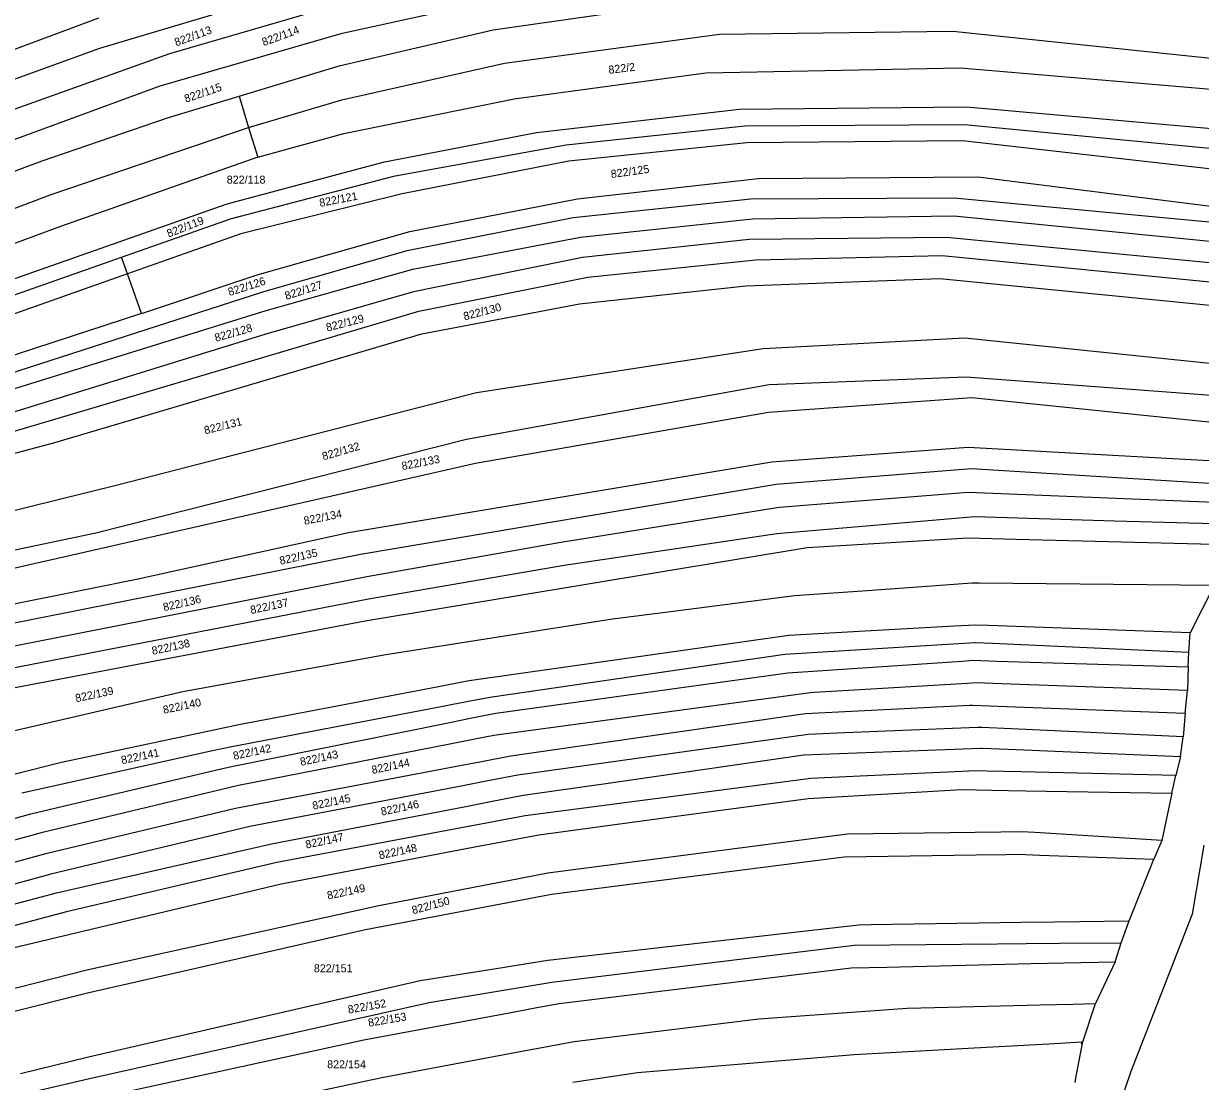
# Model space of a CAD drawing. Extents: x -580630 to -576196, y -1189024 to -1183567.
# Drawn here: x -577295.7 to -577045.8, y -1185459.8 to -1185235.3 of the extents above; entities that cross this region are included whole.
import ezdxf

# ---------------------------------------------------------------- set-up
doc = ezdxf.new("R2010")
doc.units = 0
for name, color, linetype in [('Vrstva 1', 7, 'Continuous'), ('Vrstva 13', 7, 'Continuous'), ('Vrstva 18', 7, 'Continuous'), ('Vrstva 4', 7, 'Continuous'), ('Vrstva 6', 7, 'Continuous')]:
    doc.layers.add(name, color=color, linetype=linetype)

msp = doc.modelspace()

# ---------------------------------------------------------------- linework, layer by layer
at = {"layer": 'Vrstva 1'}
for p, q in [((-577195.98, -1185236.67), (-577151.26, -1185230.19)), ((-577228.67, -1185244.27), (-577195.98, -1185236.67)), ((-577193.6, -1185243.72), (-577147.96, -1185237.55)), ((-577147.96, -1185237.55), (-577098.41, -1185236.93)), ((-577098.41, -1185236.93), (-577036.92, -1185243.39)), ((-577249.94, -1185250.73), (-577228.67, -1185244.27)), ((-577228.14, -1185251.54), (-577193.6, -1185243.72)), ((-577265.16, -1185255.36), (-577249.94, -1185250.73)), ((-577249.94, -1185250.73), (-577247.99, -1185257.41)), ((-577247.99, -1185257.41), (-577228.14, -1185251.54)), ((-577291.79, -1185264.43), (-577265.16, -1185255.36)), ((-577290.04, -1185271.7), (-577247.99, -1185257.41)), ((-577348.23, -1185285.72), (-577291.79, -1185264.43)), ((-577346.48, -1185292.79), (-577290.04, -1185271.7)), ((-577042.94, -1185354.58), (-577048.01, -1185364.64)), ((-577048.3, -1185368.7), (-577048.01, -1185364.64)), ((-577048.4, -1185371.84), (-577048.3, -1185368.7)), ((-577048.4, -1185371.84), (-577048.6, -1185376.87)), ((-577049.07, -1185381.68), (-577048.6, -1185376.87)), ((-577049.07, -1185381.68), (-577049.51, -1185386.7)), ((-577050.03, -1185390.87), (-577049.51, -1185386.7)), ((-577050.03, -1185390.87), (-577051.02, -1185394.89)), ((-577051.9, -1185398.64), (-577051.02, -1185394.89)), ((-577051.9, -1185398.64), (-577054.01, -1185408.69)), ((-577054.01, -1185408.69), (-577055.7, -1185412.68)), ((-577060.98, -1185425.7), (-577055.7, -1185412.68)), ((-577062.62, -1185430.38), (-577060.98, -1185425.7)), ((-577063.93, -1185434.4), (-577062.62, -1185430.38)), ((-577063.93, -1185434.4), (-577068.12, -1185443.28)), ((-577070.79, -1185451.4), (-577068.12, -1185443.28)), ((-577072.26, -1185459.1), (-577070.93, -1185452.15)), ((-577070.93, -1185452.15), (-577070.79, -1185451.4)), ((-577072.44, -1185460.06), (-577072.26, -1185459.1))]:
    msp.add_line(p, q, dxfattribs=at)
at = {"layer": 'Vrstva 13'}
for p, q in [((-577045.08, -1185409.66), (-577047.56, -1185424.29)), ((-577047.56, -1185424.29), (-577060.63, -1185457.67)), ((-577060.63, -1185457.67), (-577068.8, -1185482.09))]:
    msp.add_line(p, q, dxfattribs=at)
at = {"layer": 'Vrstva 4'}
msp.add_line((-577070.93, -1185452.15), (-577071.1, -1185451.42), dxfattribs=at)
at = {"layer": 'Vrstva 6'}
for p, q in [((-577225.98, -1185224.6), (-577279.63, -1185240.65)), ((-577195.67, -1185230.3), (-577228.36, -1185237.49)), ((-577264.65, -1185241.65), (-577230.51, -1185231.8)), ((-577356.86, -1185262.65), (-577279.75, -1185234.14)), ((-577228.36, -1185237.49), (-577266.81, -1185248.6)), ((-577279.63, -1185240.65), (-577428.39, -1185294.25)), ((-577306.69, -1185256.67), (-577264.65, -1185241.65)), ((-577150.83, -1185245.77), (-577096.75, -1185244.75)), ((-577096.75, -1185244.75), (-577036.69, -1185249.83)), ((-577191.54, -1185251.33), (-577150.83, -1185245.77)), ((-577266.81, -1185248.6), (-577363.54, -1185284.08)), ((-577227.72, -1185258.63), (-577191.54, -1185251.33)), ((-577095.49, -1185253.07), (-577143.71, -1185253.58)), ((-577036.22, -1185258.31), (-577095.49, -1185253.07)), ((-577143.71, -1185253.58), (-577186.83, -1185258.53)), ((-577247.99, -1185257.41), (-577245.99, -1185263.69)), ((-577180.52, -1185261.07), (-577142.59, -1185257.06)), ((-577142.59, -1185257.06), (-577095.92, -1185256.75)), ((-577095.92, -1185256.75), (-577034.72, -1185262.66)), ((-577245.99, -1185263.69), (-577227.72, -1185258.63)), ((-577186.83, -1185258.53), (-577219.42, -1185264.8)), ((-577142.17, -1185260.64), (-577179.96, -1185264.55)), ((-577096.37, -1185260.23), (-577142.17, -1185260.64)), ((-577032.89, -1185267.43), (-577096.37, -1185260.23)), ((-577216.81, -1185267.66), (-577180.52, -1185261.07)), ((-577245.99, -1185263.69), (-577287.88, -1185278.39)), ((-577219.42, -1185264.8), (-577252.59, -1185273.62)), ((-577179.96, -1185264.55), (-577215.32, -1185271.44)), ((-577251.55, -1185276.7), (-577216.81, -1185267.66)), ((-577139.76, -1185268.18), (-577093.09, -1185267.86)), ((-577093.09, -1185267.86), (-577032.52, -1185275.44)), ((-577178.1, -1185272.49), (-577139.76, -1185268.18)), ((-577215.32, -1185271.44), (-577249.56, -1185279.97)), ((-577213.67, -1185279.48), (-577178.1, -1185272.49)), ((-577179.04, -1185276.51), (-577141.3, -1185272.5)), ((-577141.3, -1185272.5), (-577098.12, -1185272.29)), ((-577098.12, -1185272.29), (-577032.65, -1185278.44)), ((-577252.59, -1185273.62), (-577345.1, -1185306.23)), ((-577274.95, -1185284.92), (-577251.55, -1185276.7)), ((-577214.3, -1185283.51), (-577179.04, -1185276.51)), ((-577177.47, -1185280.66), (-577140.97, -1185276.75)), ((-577140.97, -1185276.75), (-577098.21, -1185276.13)), ((-577098.21, -1185276.13), (-577032.99, -1185282.61)), ((-577287.88, -1185278.39), (-577347, -1185300.09)), ((-577249.56, -1185279.97), (-577273.68, -1185288.46)), ((-577246.15, -1185288.64), (-577213.67, -1185279.48)), ((-577213.04, -1185287.45), (-577177.47, -1185280.66)), ((-577141.67, -1185281.17), (-577177.04, -1185284.97)), ((-577099.72, -1185280.76), (-577141.67, -1185281.17)), ((-577033.44, -1185287.08), (-577099.72, -1185280.76)), ((-577348.19, -1185310.63), (-577274.95, -1185284.92)), ((-577273.68, -1185288.46), (-577274.95, -1185284.92)), ((-577244.93, -1185292.25), (-577214.3, -1185283.51)), ((-577177.04, -1185284.97), (-577212.91, -1185292.29)), ((-577175.91, -1185289.18), (-577140.24, -1185285.48)), ((-577140.24, -1185285.48), (-577100.65, -1185284.56)), ((-577100.65, -1185284.56), (-577033.82, -1185291.12)), ((-577244.19, -1185296.2), (-577213.04, -1185287.45)), ((-577273.68, -1185288.46), (-577336.94, -1185310.73)), ((-577270.67, -1185296.86), (-577273.68, -1185288.46)), ((-577270.67, -1185296.86), (-577246.15, -1185288.64)), ((-577211.78, -1185296.39), (-577175.91, -1185289.18)), ((-577142.38, -1185290.98), (-577101.15, -1185289.44)), ((-577101.15, -1185289.44), (-577035.33, -1185295.94)), ((-577329.44, -1185319.52), (-577244.93, -1185292.25)), ((-577212.91, -1185292.29), (-577244.27, -1185301.24)), ((-577177.64, -1185294.79), (-577142.38, -1185290.98)), ((-577211.16, -1185301.16), (-577177.64, -1185294.79)), ((-577328.69, -1185322.43), (-577244.19, -1185296.2)), ((-577270.67, -1185296.86), (-577327.07, -1185315.2)), ((-577319.42, -1185328.27), (-577211.78, -1185296.39)), ((-577244.27, -1185301.24), (-577322.5, -1185325.41)), ((-577289.08, -1185324.21), (-577211.16, -1185301.16)), ((-577095.82, -1185302.12), (-577138.7, -1185304.34)), ((-577040.41, -1185307.83), (-577095.82, -1185302.12)), ((-577138.7, -1185304.34), (-577199.56, -1185313.69)), ((-577095.54, -1185310.34), (-577137.38, -1185311.98)), ((-577042.56, -1185314.35), (-577095.54, -1185310.34)), ((-577137.38, -1185311.98), (-577201.64, -1185323.61)), ((-577199.56, -1185313.69), (-577275.79, -1185333.3)), ((-577094.37, -1185314.77), (-577137.55, -1185317.86)), ((-577042.69, -1185320.05), (-577094.37, -1185314.77)), ((-577137.55, -1185317.86), (-577199.75, -1185328.66)), ((-577389.83, -1185350.96), (-577289.08, -1185324.21)), ((-577201.64, -1185323.61), (-577280.39, -1185343.46)), ((-577095.12, -1185325.32), (-577136.86, -1185328.41)), ((-577042.72, -1185328.18), (-577095.12, -1185325.32)), ((-577199.75, -1185328.66), (-577314.8, -1185354.79)), ((-577136.86, -1185328.41), (-577226.72, -1185343.43)), ((-577135.94, -1185333.04), (-577094.51, -1185329.75)), ((-577094.51, -1185329.75), (-577042.79, -1185332.9)), ((-577224.16, -1185347.95), (-577135.94, -1185333.04)), ((-577275.79, -1185333.3), (-577337.63, -1185348.5)), ((-577095.15, -1185334.84), (-577135.25, -1185338.03)), ((-577042.79, -1185336.94), (-577095.15, -1185334.84)), ((-577135.25, -1185338.03), (-577181.63, -1185345.44)), ((-577093.72, -1185340.01), (-577135.77, -1185343.62)), ((-577064.05, -1185340.89), (-577093.72, -1185340.01)), ((-577042.9, -1185341.51), (-577064.05, -1185340.89)), ((-577280.39, -1185343.46), (-577315.66, -1185350.86)), ((-577226.72, -1185343.43), (-577271.75, -1185353.3)), ((-577181.63, -1185345.44), (-577222.84, -1185352.74)), ((-577135.77, -1185343.62), (-577180.91, -1185350.3)), ((-577095.17, -1185344.52), (-577129.3, -1185346.58)), ((-577085.03, -1185344.78), (-577095.17, -1185344.52)), ((-577043, -1185345.87), (-577085.03, -1185344.78)), ((-577311.03, -1185365.13), (-577224.16, -1185347.95)), ((-577129.3, -1185346.58), (-577223.17, -1185362.12)), ((-577180.91, -1185350.3), (-577222.45, -1185357.51)), ((-577222.84, -1185352.74), (-577310.75, -1185370.02)), ((-577271.75, -1185353.3), (-577312.87, -1185361.53)), ((-577100.01, -1185354.5), (-577117.6, -1185355.75)), ((-577094.38, -1185354.1), (-577100.01, -1185354.5)), ((-577092.8, -1185354.11), (-577094.38, -1185354.1)), ((-577042.94, -1185354.58), (-577092.8, -1185354.11)), ((-577222.45, -1185357.51), (-577309.73, -1185374.37)), ((-577132.01, -1185356.78), (-577158.81, -1185360.2)), ((-577117.6, -1185355.75), (-577132.01, -1185356.78)), ((-577158.81, -1185360.2), (-577170.67, -1185361.72)), ((-577223.17, -1185362.12), (-577306.75, -1185378.07)), ((-577170.67, -1185361.72), (-577219.22, -1185369.37)), ((-577093.56, -1185362.99), (-577098.03, -1185363.23)), ((-577090.79, -1185363.09), (-577093.56, -1185362.99)), ((-577048.01, -1185364.64), (-577090.79, -1185363.09)), ((-577133.24, -1185365.15), (-577201.11, -1185374.82)), ((-577117.02, -1185364.27), (-577133.24, -1185365.15)), ((-577098.03, -1185363.23), (-577117.02, -1185364.27)), ((-577134.09, -1185369.17), (-577097.22, -1185366.87)), ((-577097.22, -1185366.87), (-577093.68, -1185366.65)), ((-577093.68, -1185366.65), (-577089.96, -1185366.82)), ((-577089.96, -1185366.82), (-577048.3, -1185368.7)), ((-577219.22, -1185369.37), (-577261.93, -1185377.12)), ((-577149.13, -1185371.35), (-577134.09, -1185369.17)), ((-577133.45, -1185373.13), (-577096.38, -1185370.61)), ((-577096.38, -1185370.61), (-577094.07, -1185370.45)), ((-577094.07, -1185370.45), (-577089.12, -1185370.6)), ((-577089.12, -1185370.6), (-577048.4, -1185371.84)), ((-577196.23, -1185378.17), (-577149.13, -1185371.35)), ((-577202.26, -1185375.04), (-577207.64, -1185376.07)), ((-577201.11, -1185374.82), (-577202.26, -1185375.04)), ((-577195.45, -1185381.66), (-577133.45, -1185373.13)), ((-577095.3, -1185375.37), (-577127.79, -1185377.27)), ((-577093.34, -1185375.26), (-577095.3, -1185375.37)), ((-577088.04, -1185375.45), (-577093.34, -1185375.26)), ((-577048.6, -1185376.87), (-577088.04, -1185375.45)), ((-577261.93, -1185377.12), (-577305.37, -1185387.23)), ((-577207.64, -1185376.07), (-577241.77, -1185382.58)), ((-577128.61, -1185377.32), (-577195.85, -1185386.38)), ((-577127.79, -1185377.27), (-577128.61, -1185377.32)), ((-577251.47, -1185388.71), (-577206.7, -1185380.17)), ((-577206.7, -1185380.17), (-577201.34, -1185379.15)), ((-577201.34, -1185379.15), (-577196.23, -1185378.17)), ((-577129.71, -1185381.77), (-577094.8, -1185379.96)), ((-577094.8, -1185379.96), (-577094.25, -1185379.98)), ((-577094.25, -1185379.98), (-577086.97, -1185380.25)), ((-577086.97, -1185380.25), (-577049.07, -1185381.68)), ((-577241.77, -1185382.58), (-577249.65, -1185384.08)), ((-577205.88, -1185383.76), (-577200.55, -1185382.69)), ((-577200.55, -1185382.69), (-577195.45, -1185381.66)), ((-577188.87, -1185390.22), (-577129.71, -1185381.77)), ((-577249.65, -1185384.08), (-577287.67, -1185392.14)), ((-577251.59, -1185392.97), (-577205.88, -1185383.76)), ((-577093.18, -1185384.73), (-577121.3, -1185385.87)), ((-577092.23, -1185384.69), (-577093.18, -1185384.73)), ((-577085.92, -1185384.99), (-577092.23, -1185384.69)), ((-577049.51, -1185386.7), (-577085.92, -1185384.99)), ((-577199.56, -1185387.11), (-577204.88, -1185388.15)), ((-577195.85, -1185386.38), (-577199.56, -1185387.11)), ((-577129.1, -1185386.19), (-577190.79, -1185394.82)), ((-577121.3, -1185385.87), (-577129.1, -1185386.19)), ((-577296.08, -1185398.58), (-577255.6, -1185389.62)), ((-577255.6, -1185389.62), (-577251.47, -1185388.71)), ((-577204.88, -1185388.15), (-577250.05, -1185397.03)), ((-577192.23, -1185390.7), (-577188.87, -1185390.22)), ((-577171.08, -1185396.42), (-577130.07, -1185390.54)), ((-577130.07, -1185390.54), (-577092.54, -1185389.1)), ((-577092.54, -1185389.1), (-577092.18, -1185389.11)), ((-577092.18, -1185389.11), (-577084.93, -1185389.41)), ((-577084.93, -1185389.41), (-577050.03, -1185390.87)), ((-577287.67, -1185392.14), (-577298.07, -1185394.78)), ((-577254.67, -1185393.7), (-577251.59, -1185392.97)), ((-577250.73, -1185401.81), (-577203.79, -1185392.9)), ((-577203.79, -1185392.9), (-577198.48, -1185391.89)), ((-577198.48, -1185391.89), (-577192.23, -1185390.7)), ((-577271.47, -1185397.68), (-577254.67, -1185393.7)), ((-577190.79, -1185394.82), (-577197.51, -1185396.11)), ((-577128.58, -1185395.53), (-577189.2, -1185403.45)), ((-577118.04, -1185395.05), (-577128.58, -1185395.53)), ((-577093.37, -1185393.93), (-577118.04, -1185395.05)), ((-577091.09, -1185393.98), (-577093.37, -1185393.93)), ((-577083.88, -1185394.14), (-577091.09, -1185393.98)), ((-577051.02, -1185394.89), (-577083.88, -1185394.14)), ((-577294.16, -1185403.06), (-577271.47, -1185397.68)), ((-577250.05, -1185397.03), (-577291.99, -1185407.06)), ((-577202.82, -1185397.13), (-577247.64, -1185405.74)), ((-577197.51, -1185396.11), (-577202.82, -1185397.13)), ((-577189.6, -1185399.08), (-577171.08, -1185396.42)), ((-577129.15, -1185399.75), (-577096.55, -1185397.89)), ((-577096.55, -1185397.89), (-577090.18, -1185398)), ((-577090.18, -1185398), (-577082.99, -1185398.12)), ((-577201.84, -1185401.44), (-577196.56, -1185400.42)), ((-577196.56, -1185400.42), (-577189.6, -1185399.08)), ((-577158.7, -1185403.73), (-577129.15, -1185399.75)), ((-577082.99, -1185398.12), (-577051.9, -1185398.64)), ((-577308.18, -1185406.86), (-577294.16, -1185403.06)), ((-577290.74, -1185411.39), (-577250.73, -1185401.81)), ((-577243.06, -1185409.37), (-577201.84, -1185401.44)), ((-577195.61, -1185404.65), (-577200.88, -1185405.64)), ((-577189.2, -1185403.45), (-577195.61, -1185404.65)), ((-577186.32, -1185407.46), (-577158.7, -1185403.73)), ((-577291.99, -1185407.06), (-577307.17, -1185411.18)), ((-577247.64, -1185405.74), (-577289.9, -1185415.82)), ((-577200.88, -1185405.64), (-577241.95, -1185413.33)), ((-577194.61, -1185409.03), (-577186.32, -1185407.46)), ((-577120.79, -1185407.35), (-577135.49, -1185409.26)), ((-577088.17, -1185406.9), (-577120.79, -1185407.35)), ((-577083.77, -1185406.84), (-577088.17, -1185406.9)), ((-577081.01, -1185407.01), (-577083.77, -1185406.84)), ((-577054.01, -1185408.69), (-577081.01, -1185407.01)), ((-577288.71, -1185419.76), (-577243.06, -1185409.37)), ((-577241.04, -1185417.86), (-577199.87, -1185410.03)), ((-577199.87, -1185410.03), (-577194.61, -1185409.03)), ((-577135.49, -1185409.26), (-577184.43, -1185415.63)), ((-577306.15, -1185415.6), (-577295.35, -1185412.65)), ((-577295.35, -1185412.65), (-577290.74, -1185411.39)), ((-577183.59, -1185420.06), (-577121.5, -1185412.13)), ((-577121.5, -1185412.13), (-577093.46, -1185411.75)), ((-577093.46, -1185411.75), (-577087.09, -1185411.66)), ((-577087.09, -1185411.66), (-577084.48, -1185411.62)), ((-577084.48, -1185411.62), (-577079.94, -1185411.79)), ((-577079.94, -1185411.79), (-577055.7, -1185412.68)), ((-577241.95, -1185413.33), (-577286.57, -1185423.82)), ((-577289.9, -1185415.82), (-577305.15, -1185419.99)), ((-577302.26, -1185432.44), (-577241.04, -1185417.86)), ((-577192.78, -1185417.23), (-577197.99, -1185418.23)), ((-577184.43, -1185415.63), (-577192.78, -1185417.23)), ((-577304.22, -1185423.94), (-577288.71, -1185419.76)), ((-577197.99, -1185418.23), (-577220.31, -1185422.52)), ((-577191.79, -1185421.62), (-577183.59, -1185420.06)), ((-577220.31, -1185422.52), (-577282.31, -1185436.21)), ((-577208.53, -1185424.8), (-577196.99, -1185422.61)), ((-577196.99, -1185422.61), (-577191.79, -1185421.62)), ((-577286.57, -1185423.82), (-577303.23, -1185428.22)), ((-577223.1, -1185427.57), (-577208.53, -1185424.8)), ((-577226.85, -1185428.42), (-577223.1, -1185427.57)), ((-577170.69, -1185432.53), (-577118.37, -1185426.55)), ((-577118.37, -1185426.55), (-577115.78, -1185426.51)), ((-577115.78, -1185426.51), (-577083.83, -1185426.04)), ((-577083.83, -1185426.04), (-577076.78, -1185425.94)), ((-577076.78, -1185425.94), (-577060.98, -1185425.7)), ((-577246.38, -1185432.88), (-577226.85, -1185428.42)), ((-577088.93, -1185430.63), (-577082.79, -1185430.57)), ((-577082.79, -1185430.57), (-577075.75, -1185430.5)), ((-577075.75, -1185430.5), (-577062.62, -1185430.38)), ((-577282.12, -1185441.04), (-577246.38, -1185432.88)), ((-577184.38, -1185434.1), (-577170.69, -1185432.53)), ((-577158.73, -1185435.73), (-577119.37, -1185430.92)), ((-577119.37, -1185430.92), (-577088.93, -1185430.63)), ((-577194.01, -1185435.63), (-577188.85, -1185434.81)), ((-577188.85, -1185434.81), (-577184.38, -1185434.1)), ((-577120.02, -1185435.72), (-577112.31, -1185435.54)), ((-577112.31, -1185435.54), (-577081.84, -1185434.82)), ((-577081.84, -1185434.82), (-577074.83, -1185434.66)), ((-577074.83, -1185434.66), (-577063.93, -1185434.4)), ((-577282.31, -1185436.21), (-577300.34, -1185440.81)), ((-577211.5, -1185438.41), (-577194.01, -1185435.63)), ((-577183.56, -1185438.77), (-577158.73, -1185435.73)), ((-577182.02, -1185443.26), (-577120.02, -1185435.72)), ((-577281.93, -1185454.59), (-577211.5, -1185438.41)), ((-577209.57, -1185443.03), (-577192.93, -1185440.3)), ((-577192.93, -1185440.3), (-577187.79, -1185439.46)), ((-577187.79, -1185439.46), (-577183.56, -1185438.77)), ((-577299.31, -1185445.31), (-577282.12, -1185441.04)), ((-577281.74, -1185459.16), (-577209.57, -1185443.03)), ((-577223.45, -1185451), (-577191.84, -1185445.1)), ((-577191.84, -1185445.1), (-577186.76, -1185444.15)), ((-577186.76, -1185444.15), (-577182.02, -1185443.26)), ((-577139.62, -1185446.53), (-577108.08, -1185444.27)), ((-577108.08, -1185444.27), (-577102.32, -1185444.13)), ((-577102.32, -1185444.13), (-577079.86, -1185443.57)), ((-577079.86, -1185443.57), (-577072.88, -1185443.4)), ((-577072.88, -1185443.4), (-577068.12, -1185443.28)), ((-577178.8, -1185451.33), (-577139.62, -1185446.53)), ((-577291.32, -1185465.72), (-577223.45, -1185451)), ((-577189.94, -1185453.41), (-577184.89, -1185452.47)), ((-577184.89, -1185452.47), (-577178.8, -1185451.33)), ((-577119.36, -1185454.09), (-577093.87, -1185452.68)), ((-577093.87, -1185452.68), (-577078, -1185451.8)), ((-577078, -1185451.8), (-577071.1, -1185451.42)), ((-577071.1, -1185451.42), (-577070.79, -1185451.4)), ((-577296.35, -1185458.15), (-577281.93, -1185454.59)), ((-577219.64, -1185458.97), (-577189.94, -1185453.41)), ((-577165.39, -1185457.93), (-577119.36, -1185454.09)), ((-577179.06, -1185459.94), (-577165.39, -1185457.93)), ((-577295.37, -1185462.39), (-577281.74, -1185459.16)), ((-577262, -1185467.96), (-577219.64, -1185458.97))]:
    msp.add_line(p, q, dxfattribs=at)

# ---------------------------------------------------------------- texts
at = {"layer": 'Vrstva 18'}
for s, rotation, p in [('822/113', 20.11082, (-577263.31, -1185240.175)), ('822/114', 20.11082, (-577244.728, -1185240.145)), ('822/2', 6.7609, (-577171.425, -1185246.003)), ('822/115', 18.67843, (-577261.248, -1185252.129)), ('822/125', 7.96411, (-577170.902, -1185268.129)), ('822/121', 11.00079, (-577232.743, -1185274.243)), ('822/119', 21.48592, (-577264.902, -1185280.761)), ('822/126', 17.81899, (-577251.995, -1185293.172)), ('822/127', 17.81899, (-577239.927, -1185293.979)), ('822/130', 14.78231, (-577202.074, -1185298.322)), ('822/129', 14.55313, (-577231.24, -1185300.704)), ('822/128', 15.98552, (-577254.879, -1185302.883)), ('822/131', 14.03747, (-577257.156, -1185322.512)), ('822/132', 16.272, (-577232.046, -1185328.035)), ('822/133', 11.00079, (-577215.273, -1185330.088)), ('822/134', 11.00079, (-577236.058, -1185341.692)), ('822/135', 12.66237, (-577241.166, -1185350.176)), ('822/136', 12.66237, (-577265.9, -1185360.036)), ('822/137', 11.97482, (-577247.383, -1185360.632)), ('822/138', 11.97482, (-577268.312, -1185369.284)), ('822/139', 11.97482, (-577284.542, -1185379.36)), ('822/140', 11.97482, (-577265.933, -1185381.818)), ('822/141', 11.97482, (-577274.806, -1185392.5)), ('822/142', 11.97482, (-577251.029, -1185391.578)), ('822/143', 11.97482, (-577236.822, -1185392.85)), ('822/144', 11.97482, (-577221.627, -1185394.582)), ('822/145', 11.97482, (-577234.203, -1185402.162)), ('822/146', 11.97482, (-577219.667, -1185403.422)), ('822/147', 11.97482, (-577235.668, -1185410.414)), ('822/148', 11.97482, (-577220.097, -1185412.686)), ('822/149', 11.97482, (-577231.077, -1185421.222)), ('822/150', 15.06879, (-577213.029, -1185424.345)), ('822/152', 9.79758, (-577226.709, -1185445.41)), ('822/153', 9.79758, (-577222.402, -1185448.222))]:
    msp.add_text(s, height=1.7, rotation=rotation, dxfattribs=at).set_placement(p)
for s, p in [('822/118', (-577252.58, -1185269.3)), ('822/151', (-577234.077, -1185436.65)), ('822/154', (-577231.245, -1185457.03))]:
    msp.add_text(s, height=1.7, dxfattribs=at).set_placement(p)

doc.saveas('drawing.dxf')
